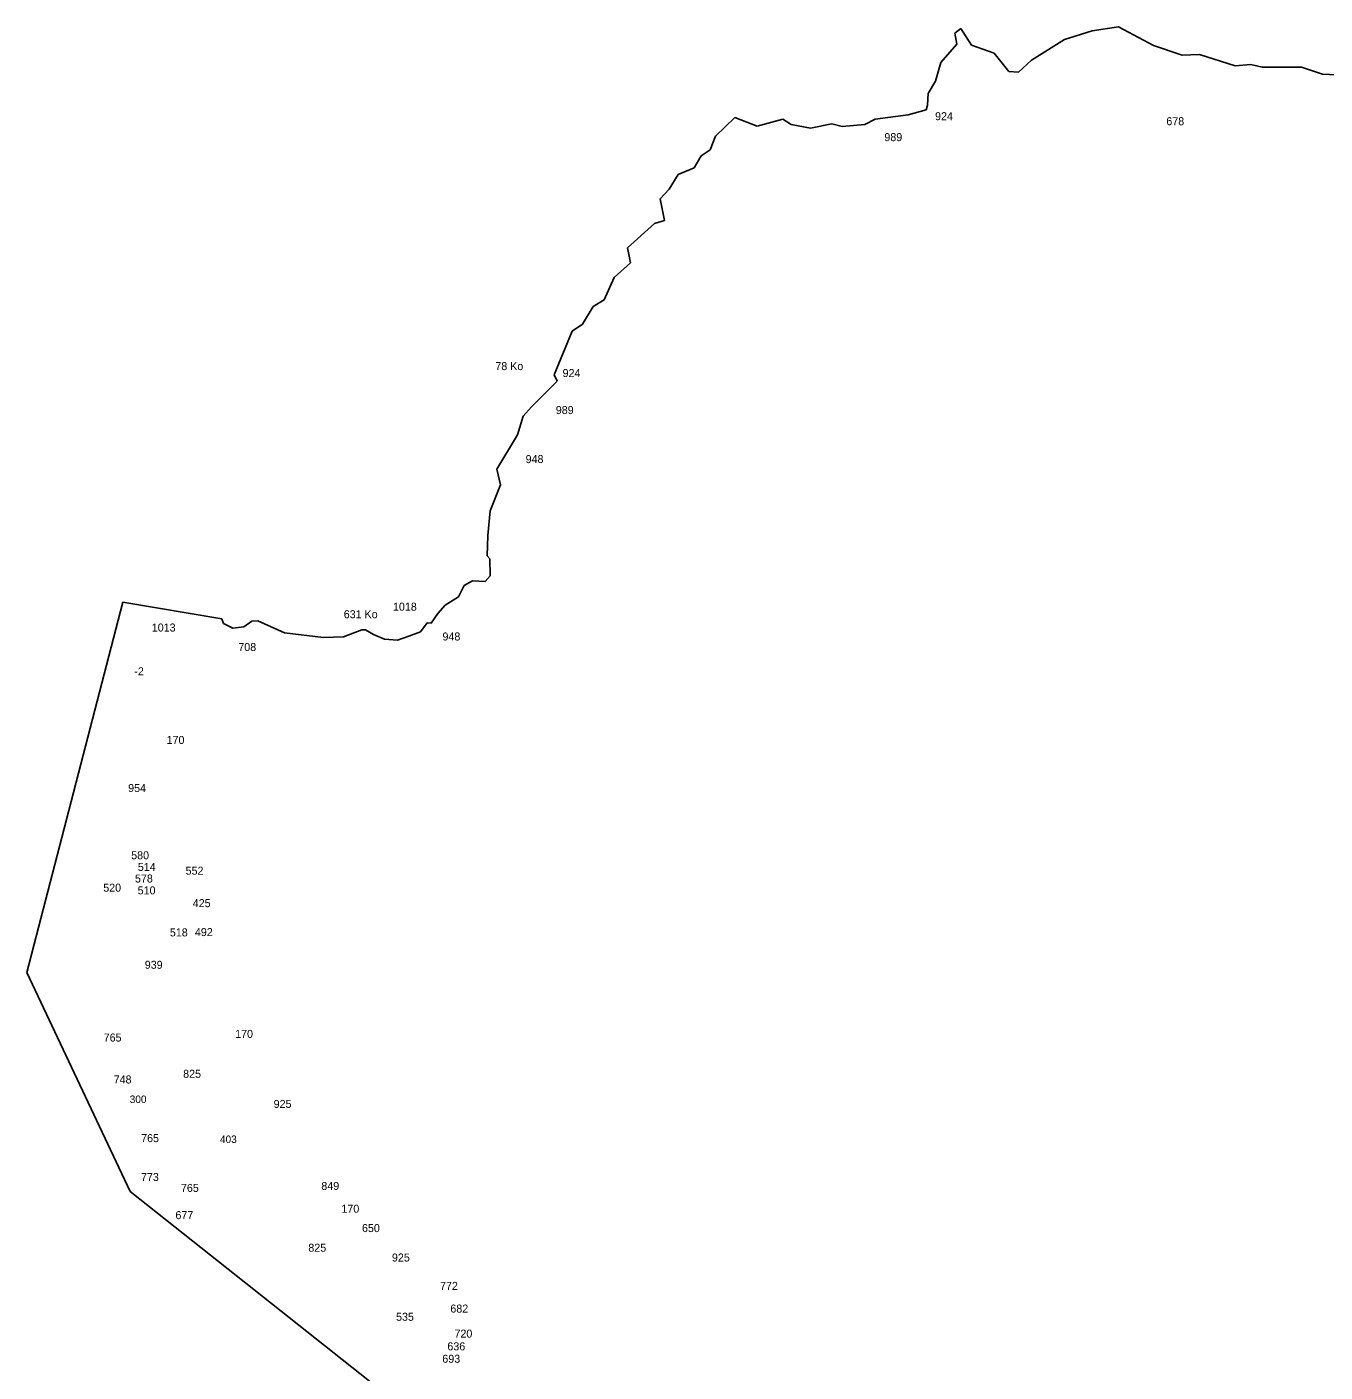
# Model space of a CAD drawing. Extents: x -779790 to -775735, y -971779 to -967735.
# Drawn here: x -779790 to -777845, y -969752 to -967735 of the extents above; entities that cross this region are included whole.
import ezdxf

# ---------------------------------------------------------------- set-up
doc = ezdxf.new("R2010")
doc.units = 0
doc.layers.add('Vrstva 15', color=7, linetype='Continuous')
doc.layers.add('Vrstva 24', color=7, linetype='Continuous')

msp = doc.modelspace()

# ---------------------------------------------------------------- linework, layer by layer
at = {"layer": 'Vrstva 15'}
for p, q in [((-778399.33, -967744.58), (-778390.45, -967737.72)), ((-778390.45, -967737.72), (-778374.7, -967762.75)), ((-778235.44, -967754.27), (-778193.85, -967741.34)), ((-778193.85, -967741.34), (-778154.29, -967735.29)), ((-778154.29, -967735.29), (-778101.81, -967763.14)), ((-778420.32, -967788.59), (-778396.5, -967761.14)), ((-778396.5, -967761.14), (-778399.33, -967744.58)), ((-778284.69, -967784.95), (-778235.44, -967754.27)), ((-778374.7, -967762.75), (-778340.39, -967774.46)), ((-778340.39, -967774.46), (-778318.59, -967802.31)), ((-778101.81, -967763.14), (-778058.62, -967777.67)), ((-778058.62, -967777.67), (-778032.79, -967776.46)), ((-778032.79, -967776.46), (-777979.5, -967793.82)), ((-778428.39, -967816.84), (-778420.32, -967788.59)), ((-778318.59, -967802.31), (-778304.06, -967803.12)), ((-778304.06, -967803.12), (-778284.69, -967784.95)), ((-777979.5, -967793.82), (-777956.09, -967791.4)), ((-777956.09, -967791.4), (-777939.13, -967795.44)), ((-777939.13, -967795.44), (-777879.79, -967795.44)), ((-777879.79, -967795.44), (-777848.31, -967806.34)), ((-778439.69, -967835.01), (-778428.39, -967816.84)), ((-777848.31, -967806.34), (-777817.63, -967807.55)), ((-778440.49, -967852.76), (-778439.69, -967835.01)), ((-778469.56, -967867.3), (-778442.51, -967859.63)), ((-778442.51, -967859.63), (-778440.49, -967852.76)), ((-778758.19, -967899.19), (-778729.53, -967871.34)), ((-778729.53, -967871.34), (-778695.62, -967884.25)), ((-778695.62, -967884.25), (-778657.27, -967873.76)), ((-778657.27, -967873.76), (-778644.76, -967881.43)), ((-778644.76, -967881.43), (-778615.69, -967887.08)), ((-778615.69, -967887.08), (-778583.8, -967880.62)), ((-778583.8, -967880.62), (-778568.46, -967884.65)), ((-778568.46, -967884.65), (-778534.55, -967881.83)), ((-778534.55, -967881.83), (-778519.21, -967873.35)), ((-778519.21, -967873.35), (-778469.56, -967867.3)), ((-778766.26, -967919.78), (-778758.19, -967899.19)), ((-778779.99, -967928.66), (-778766.26, -967919.78)), ((-778790.48, -967946.42), (-778779.99, -967928.66)), ((-778827.62, -967978.71), (-778814.3, -967956.51)), ((-778814.3, -967956.51), (-778790.48, -967946.42)), ((-778841.34, -967992.84), (-778827.62, -967978.71)), ((-778834.48, -968025.54), (-778841.34, -967992.84)), ((-778890.18, -968066.71), (-778849.82, -968029.98)), ((-778849.82, -968029.98), (-778834.48, -968025.54)), ((-778885.74, -968088.91), (-778890.18, -968066.71)), ((-778910.36, -968111.11), (-778885.74, -968088.91)), ((-778925.3, -968144.62), (-778910.36, -968111.11)), ((-778941.85, -968154.31), (-778925.3, -968144.62)), ((-778957.59, -968180.95), (-778941.85, -968154.31)), ((-778972.93, -968191.44), (-778957.59, -968180.95)), ((-778999.98, -968256.84), (-778972.93, -968191.44)), ((-779034.29, -968304.88), (-778995.54, -968266.12)), ((-778995.54, -968266.12), (-778999.98, -968256.84)), ((-779046.4, -968319), (-779034.29, -968304.88)), ((-779054.88, -968346.85), (-779046.4, -968319)), ((-779085.96, -968398.52), (-779054.88, -968346.85)), ((-779080.71, -968421.94), (-779085.96, -968398.52)), ((-779096.05, -968460.69), (-779080.71, -968421.94)), ((-779099.68, -968497.83), (-779096.05, -968460.69)), ((-779100.49, -968528.1), (-779099.68, -968497.83)), ((-779096.45, -968532.54), (-779100.49, -968528.1)), ((-779096.05, -968558.38), (-779096.45, -968532.54)), ((-779135.21, -968572.5), (-779122.69, -968565.64)), ((-779122.69, -968565.64), (-779103.72, -968566.45)), ((-779103.72, -968566.45), (-779096.05, -968558.38)), ((-779143.68, -968589.46), (-779135.21, -968572.5)), ((-779790.36, -969152.99), (-779646.65, -968597.54)), ((-779646.65, -968597.54), (-779498.1, -968622.76)), ((-779174.36, -968614.49), (-779163.46, -968601.97)), ((-779163.46, -968601.97), (-779143.68, -968589.46)), ((-779498.1, -968622.76), (-779495.68, -968629.63)), ((-779495.68, -968629.63), (-779481.55, -968636.49)), ((-779465, -968634.87), (-779453.29, -968625.99)), ((-779453.29, -968625.99), (-779444.41, -968625.59)), ((-779444.41, -968625.59), (-779404.05, -968643.75)), ((-779200.6, -968641.94), (-779190.51, -968628.61)), ((-779190.51, -968628.61), (-779184.45, -968629.02)), ((-779184.45, -968629.02), (-779174.36, -968614.49)), ((-779481.55, -968636.49), (-779465, -968634.87)), ((-779404.05, -968643.75), (-779345.92, -968650.62)), ((-779345.92, -968650.62), (-779315.85, -968649.71)), ((-779315.85, -968649.71), (-779288.19, -968639.21)), ((-779288.19, -968639.21), (-779282.74, -968639.21)), ((-779282.74, -968639.21), (-779270.63, -968646.28)), ((-779270.63, -968646.28), (-779254.29, -968653.34)), ((-779234.91, -968654.55), (-779218.16, -968648.7)), ((-779218.16, -968648.7), (-779200.6, -968641.94)), ((-779254.29, -968653.34), (-779234.91, -968654.55)), ((-779635.35, -969480.99), (-779790.36, -969152.99)), ((-779276.92, -969765.66), (-779635.35, -969480.99))]:
    msp.add_line(p, q, dxfattribs=at)

# ---------------------------------------------------------------- texts
at = {"layer": 'Vrstva 24'}
for s, height, p in [('924', 12, (-778429.194, -967875.15)), ('678', 12, (-778082.567, -967882.68)), ('989', 12, (-778505.187, -967906.53)), ('78 Ko', 12, (-779088.29, -968249.79)), ('924', 12, (-778987.474, -968260.21)), ('989', 12, (-778997.637, -968315.68)), ('948', 12, (-779042.863, -968389.16)), ('1018', 12, (-779241.689, -968610.44)), ('1013', 12, (-779603.199, -968641.65)), ('631 Ko', 12, (-779315.483, -968621.75)), ('948', 12, (-779167.513, -968655.09)), ('708', 12, (-779473.493, -968670.91)), ('-2', 12, (-779629.417, -968707.28)), ('170', 12, (-779581.025, -968810.21)), ('954', 12, (-779638.634, -968882.29)), ('580', 12, (-779634.077, -968983.09)), ('514', 12, (-779624.129, -969000.57)), ('578', 12, (-779628.371, -969017.91)), ('552', 12, (-779552.495, -969006.23)), ('520', 12, (-779675.977, -969031.65)), ('510', 12, (-779624.339, -969035.72)), ('425', 12, (-779541.777, -969054.86)), ('518', 12, (-779576.086, -969098.71)), ('492', 12, (-779538.583, -969098.24)), ('939', 12, (-779613.727, -969147.21)), ('765', 12, (-779675.307, -969256.3)), ('170', 12, (-779478.255, -969250.88)), ('748', 12, (-779660.333, -969319.15)), ('825', 12, (-779556.165, -969310.64)), ('300', 11.25, (-779636.244, -969348.473)), ('925', 12, (-779420.551, -969355.85)), ('765', 12, (-779619.187, -969407.12)), ('403', 11.25, (-779500.943, -969408.403)), ('773', 12, (-779619.387, -969465.35)), ('765', 12, (-779559.507, -969481.76)), ('849', 12, (-779349.094, -969478.81)), ('677', 12, (-779567.733, -969522.51)), ('170', 12, (-779318.965, -969512.92)), ('650', 12, (-779288.153, -969541.95)), ('825', 12, (-779368.545, -969571.37)), ('925', 12, (-779243.271, -969586.06)), ('772', 12, (-779171.187, -969628.62)), ('682', 12, (-779155.711, -969662.62)), ('535', 12, (-779237.075, -969674.91)), ('720', 12, (-779149.523, -969700.15)), ('636', 12, (-779160.187, -969719.23)), ('693', 12, (-779167.746, -969737.85))]:
    msp.add_text(s, height=height, dxfattribs=at).set_placement(p)

doc.saveas('drawing.dxf')
